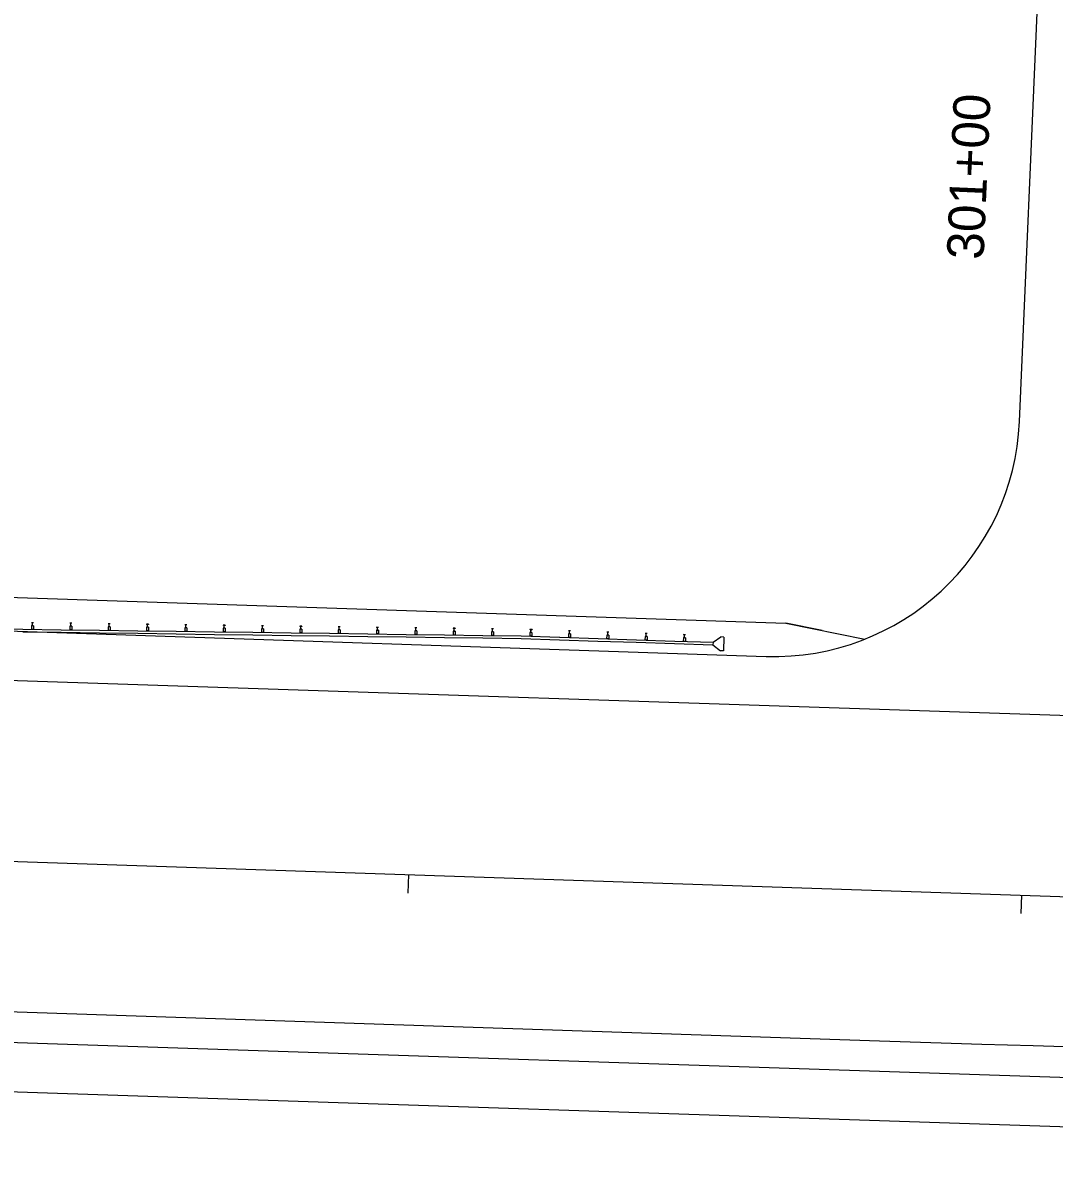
# Model space of a CAD drawing. Extents: x 976639 to 985448, y 1524031 to 1526806.
# Drawn here: x 978186 to 978354.1, y 1526423 to 1526609.3 of the extents above; entities that cross this region are included whole.
import ezdxf

# ---------------------------------------------------------------- set-up
doc = ezdxf.new("R2010")
doc.units = 0
for name, color, linetype in [('B_Steel', 7, 'Continuous'), ('R_Horz Alg', 7, 'Continuous'), ('R_Horz Alg Annot', 7, 'Continuous'), ('R_Horz Alg Annot_Cross Street', 7, 'Continuous'), ('R_Proposed Road_Lane', 7, 'Continuous'), ('R_Proposed Road_Shoulder', 7, 'Continuous'), ('S_WORKING_LINES', 7, 'Continuous')]:
    doc.layers.add(name, color=color, linetype=linetype)

msp = doc.modelspace()

# ---------------------------------------------------------------- linework, layer by layer
at = {"layer": 'B_Steel'}
for p, q in [((978179.73, 1526510.61), (978185.98, 1526510.53)), ((978185.98, 1526510.53), (978192.23, 1526510.44)), ((978187.54, 1526511.11), (978187.39, 1526511.11)), ((978187.39, 1526511.11), (978187.39, 1526511.09)), ((978187.73, 1526511.09), (978187.39, 1526511.09)), ((978187.39, 1526511.09), (978187.39, 1526510.51)), ((978187.72, 1526510.5), (978187.39, 1526510.51)), ((978187.73, 1526511.59), (978187.4, 1526511.59)), ((978187.4, 1526511.59), (978187.4, 1526511.58)), ((978187.55, 1526511.57), (978187.4, 1526511.58)), ((978187.55, 1526511.11), (978187.56, 1526511.57)), ((978187.57, 1526511.11), (978187.57, 1526511.57)), ((978187.73, 1526511.57), (978187.58, 1526511.57)), ((978187.73, 1526511.1), (978187.58, 1526511.1)), ((978187.73, 1526511.09), (978187.72, 1526510.5)), ((978187.73, 1526511.59), (978187.73, 1526511.57)), ((978187.73, 1526511.1), (978187.73, 1526511.09)), ((978192.23, 1526510.44), (978198.48, 1526510.36)), ((978193.64, 1526511.01), (978193.63, 1526510.43)), ((978193.97, 1526510.42), (978193.63, 1526510.43)), ((978193.79, 1526511.02), (978193.64, 1526511.02)), ((978193.64, 1526511.02), (978193.64, 1526511.01)), ((978193.98, 1526511), (978193.64, 1526511.01)), ((978193.98, 1526511.5), (978193.65, 1526511.51)), ((978193.65, 1526511.51), (978193.65, 1526511.49)), ((978193.8, 1526511.49), (978193.65, 1526511.49)), ((978193.8, 1526511.03), (978193.81, 1526511.48)), ((978193.82, 1526511.03), (978193.82, 1526511.48)), ((978193.98, 1526511.49), (978193.83, 1526511.49)), ((978193.98, 1526511.02), (978193.83, 1526511.02)), ((978193.98, 1526511), (978193.97, 1526510.42)), ((978193.98, 1526511.5), (978193.98, 1526511.49)), ((978193.98, 1526511.02), (978193.98, 1526511)), ((978198.48, 1526510.36), (978204.73, 1526510.28)), ((978199.89, 1526510.92), (978199.88, 1526510.34)), ((978200.22, 1526510.34), (978199.88, 1526510.34)), ((978200.04, 1526510.94), (978199.89, 1526510.94)), ((978199.89, 1526510.94), (978199.89, 1526510.92)), ((978200.22, 1526510.92), (978199.89, 1526510.92)), ((978200.23, 1526511.42), (978199.9, 1526511.42)), ((978199.9, 1526511.42), (978199.9, 1526511.41)), ((978200.05, 1526511.41), (978199.9, 1526511.41)), ((978200.05, 1526510.95), (978200.06, 1526511.4)), ((978200.07, 1526510.95), (978200.07, 1526511.4)), ((978200.23, 1526511.4), (978200.08, 1526511.41)), ((978200.23, 1526510.94), (978200.08, 1526510.94)), ((978200.23, 1526510.94), (978200.22, 1526510.92)), ((978200.22, 1526510.92), (978200.22, 1526510.34)), ((978200.23, 1526511.42), (978200.23, 1526511.4)), ((978204.73, 1526510.28), (978210.98, 1526510.19)), ((978206.14, 1526510.84), (978206.13, 1526510.26)), ((978206.47, 1526510.25), (978206.13, 1526510.26)), ((978206.29, 1526510.85), (978206.14, 1526510.86)), ((978206.14, 1526510.86), (978206.14, 1526510.84)), ((978206.47, 1526510.84), (978206.14, 1526510.84)), ((978206.48, 1526511.34), (978206.15, 1526511.34)), ((978206.15, 1526511.34), (978206.15, 1526511.32)), ((978206.3, 1526511.32), (978206.15, 1526511.32)), ((978206.3, 1526510.86), (978206.31, 1526511.31)), ((978206.32, 1526510.86), (978206.32, 1526511.31)), ((978206.47, 1526510.85), (978206.32, 1526510.85)), ((978206.48, 1526511.32), (978206.33, 1526511.32)), ((978206.47, 1526510.85), (978206.47, 1526510.84)), ((978206.47, 1526510.84), (978206.47, 1526510.25)), ((978206.48, 1526511.34), (978206.48, 1526511.32)), ((978210.98, 1526510.19), (978217.23, 1526510.11)), ((978212.39, 1526510.76), (978212.38, 1526510.17)), ((978212.72, 1526510.17), (978212.38, 1526510.17)), ((978212.54, 1526510.77), (978212.39, 1526510.77)), ((978212.39, 1526510.77), (978212.39, 1526510.76)), ((978212.72, 1526510.75), (978212.39, 1526510.76)), ((978212.73, 1526511.25), (978212.4, 1526511.26)), ((978212.4, 1526511.26), (978212.4, 1526511.24)), ((978212.55, 1526511.24), (978212.4, 1526511.24)), ((978212.55, 1526510.78), (978212.56, 1526511.23)), ((978212.57, 1526510.78), (978212.57, 1526511.23)), ((978212.72, 1526510.77), (978212.57, 1526510.77)), ((978212.73, 1526511.24), (978212.58, 1526511.24)), ((978212.72, 1526510.77), (978212.72, 1526510.75)), ((978212.72, 1526510.75), (978212.72, 1526510.17)), ((978212.73, 1526511.25), (978212.73, 1526511.24)), ((978218.64, 1526510.67), (978218.63, 1526510.09)), ((978218.79, 1526510.69), (978218.64, 1526510.69)), ((978218.64, 1526510.69), (978218.64, 1526510.67)), ((978218.97, 1526510.67), (978218.64, 1526510.67)), ((978218.98, 1526511.17), (978218.65, 1526511.17)), ((978218.65, 1526511.17), (978218.65, 1526511.16)), ((978218.8, 1526511.15), (978218.65, 1526511.16)), ((978218.8, 1526510.69), (978218.81, 1526511.15)), ((978218.82, 1526510.69), (978218.82, 1526511.15)), ((978218.97, 1526510.68), (978218.82, 1526510.69)), ((978218.98, 1526511.15), (978218.83, 1526511.15)), ((978218.97, 1526510.68), (978218.97, 1526510.67)), ((978218.97, 1526510.67), (978218.97, 1526510.09)), ((978218.98, 1526511.17), (978218.98, 1526511.15)), ((978224.89, 1526510.59), (978224.88, 1526510.01)), ((978225.04, 1526510.6), (978224.89, 1526510.6)), ((978224.89, 1526510.6), (978224.89, 1526510.59)), ((978225.22, 1526510.58), (978224.89, 1526510.59)), ((978225.23, 1526511.08), (978224.9, 1526511.09)), ((978224.9, 1526511.09), (978224.9, 1526511.07)), ((978225.05, 1526511.07), (978224.9, 1526511.07)), ((978225.05, 1526510.61), (978225.05, 1526511.06)), ((978225.06, 1526510.61), (978225.07, 1526511.06)), ((978225.22, 1526510.6), (978225.07, 1526510.6)), ((978225.23, 1526511.07), (978225.08, 1526511.07)), ((978225.22, 1526510.58), (978225.21, 1526510)), ((978225.22, 1526510.6), (978225.22, 1526510.58)), ((978225.23, 1526511.08), (978225.23, 1526511.07)), ((978231.14, 1526510.51), (978231.13, 1526509.92)), ((978231.29, 1526510.52), (978231.14, 1526510.52)), ((978231.14, 1526510.52), (978231.14, 1526510.51)), ((978231.47, 1526510.5), (978231.14, 1526510.51)), ((978231.48, 1526511), (978231.15, 1526511.01)), ((978231.15, 1526511.01), (978231.15, 1526510.99)), ((978231.3, 1526510.99), (978231.15, 1526510.99)), ((978231.3, 1526510.53), (978231.3, 1526510.98)), ((978231.31, 1526510.53), (978231.32, 1526510.98)), ((978231.47, 1526510.52), (978231.32, 1526510.52)), ((978231.48, 1526510.98), (978231.33, 1526510.99)), ((978231.47, 1526510.5), (978231.46, 1526509.92)), ((978231.47, 1526510.52), (978231.47, 1526510.5)), ((978231.48, 1526511), (978231.48, 1526510.98)), ((978237.39, 1526510.42), (978237.38, 1526509.84)), ((978237.4, 1526510.92), (978237.39, 1526510.91)), ((978237.55, 1526510.9), (978237.39, 1526510.91)), ((978237.54, 1526510.43), (978237.39, 1526510.44)), ((978237.39, 1526510.44), (978237.39, 1526510.42)), ((978237.72, 1526510.42), (978237.39, 1526510.42)), ((978237.73, 1526510.92), (978237.4, 1526510.92)), ((978237.55, 1526510.44), (978237.55, 1526510.9)), ((978237.56, 1526510.44), (978237.57, 1526510.89)), ((978237.72, 1526510.43), (978237.57, 1526510.43)), ((978237.73, 1526510.9), (978237.58, 1526510.9)), ((978237.72, 1526510.42), (978237.71, 1526509.83)), ((978237.72, 1526510.43), (978237.72, 1526510.42)), ((978237.73, 1526510.92), (978237.73, 1526510.9)), ((978243.64, 1526510.34), (978243.63, 1526509.75)), ((978243.98, 1526510.83), (978243.64, 1526510.84)), ((978243.64, 1526510.84), (978243.64, 1526510.82)), ((978243.8, 1526510.82), (978243.64, 1526510.82)), ((978243.79, 1526510.35), (978243.64, 1526510.35)), ((978243.64, 1526510.35), (978243.64, 1526510.34)), ((978243.97, 1526510.33), (978243.64, 1526510.34)), ((978243.8, 1526510.36), (978243.8, 1526510.81)), ((978243.81, 1526510.36), (978243.82, 1526510.81)), ((978243.97, 1526510.35), (978243.82, 1526510.35)), ((978243.98, 1526510.82), (978243.83, 1526510.82)), ((978243.97, 1526510.33), (978243.96, 1526509.75)), ((978243.97, 1526510.35), (978243.97, 1526510.33)), ((978243.98, 1526510.83), (978243.98, 1526510.82)), ((978249.89, 1526510.25), (978249.88, 1526509.67)), ((978250.23, 1526510.75), (978249.89, 1526510.75)), ((978249.89, 1526510.75), (978249.89, 1526510.74)), ((978250.04, 1526510.74), (978249.89, 1526510.74)), ((978250.04, 1526510.27), (978249.89, 1526510.27)), ((978249.89, 1526510.27), (978249.89, 1526510.25)), ((978250.22, 1526510.25), (978249.89, 1526510.25)), ((978250.05, 1526510.27), (978250.05, 1526510.73)), ((978250.06, 1526510.27), (978250.07, 1526510.73)), ((978250.22, 1526510.26), (978250.07, 1526510.27)), ((978250.23, 1526510.73), (978250.08, 1526510.73)), ((978250.22, 1526510.25), (978250.21, 1526509.67)), ((978250.22, 1526510.26), (978250.22, 1526510.25)), ((978250.23, 1526510.75), (978250.23, 1526510.73)), ((978256.14, 1526510.17), (978256.13, 1526509.59)), ((978256.48, 1526510.67), (978256.14, 1526510.67)), ((978256.14, 1526510.67), (978256.14, 1526510.65)), ((978256.29, 1526510.65), (978256.14, 1526510.65)), ((978256.29, 1526510.18), (978256.14, 1526510.18)), ((978256.14, 1526510.18), (978256.14, 1526510.17)), ((978256.47, 1526510.17), (978256.14, 1526510.17)), ((978256.3, 1526510.19), (978256.3, 1526510.64)), ((978256.31, 1526510.19), (978256.32, 1526510.64)), ((978256.47, 1526510.18), (978256.32, 1526510.18)), ((978256.48, 1526510.65), (978256.33, 1526510.65)), ((978256.47, 1526510.17), (978256.46, 1526509.58)), ((978256.47, 1526510.18), (978256.47, 1526510.17)), ((978256.48, 1526510.67), (978256.48, 1526510.65)), ((978262.73, 1526510.58), (978262.39, 1526510.59)), ((978262.39, 1526510.59), (978262.39, 1526510.57)), ((978262.54, 1526510.57), (978262.39, 1526510.57)), ((978262.55, 1526510.11), (978262.55, 1526510.56)), ((978262.56, 1526510.11), (978262.57, 1526510.56)), ((978262.73, 1526510.57), (978262.58, 1526510.57)), ((978262.73, 1526510.58), (978262.73, 1526510.57)), ((978269, 1526510.46), (978268.66, 1526510.47)), ((978268.66, 1526510.47), (978268.66, 1526510.46)), ((978268.81, 1526510.45), (978268.66, 1526510.46)), ((978268.81, 1526509.99), (978268.82, 1526510.44)), ((978268.82, 1526509.99), (978268.84, 1526510.44)), ((978269, 1526510.45), (978268.85, 1526510.45)), ((978269, 1526510.46), (978269, 1526510.45)), ((978275.29, 1526510.25), (978274.95, 1526510.26)), ((978274.95, 1526510.26), (978274.95, 1526510.25)), ((978275.1, 1526510.24), (978274.95, 1526510.25)), ((978275.1, 1526509.78), (978275.11, 1526510.23)), ((978275.11, 1526509.78), (978275.13, 1526510.23)), ((978275.29, 1526510.24), (978275.14, 1526510.24)), ((978275.29, 1526510.25), (978275.29, 1526510.24)), ((978185.97, 1526510.11), (978192.22, 1526510.03)), ((978192.22, 1526510.03), (978198.47, 1526509.94)), ((978198.47, 1526509.94), (978204.72, 1526509.86)), ((978204.72, 1526509.86), (978210.97, 1526509.78)), ((978210.97, 1526509.78), (978217.22, 1526509.69)), ((978217.22, 1526509.69), (978223.47, 1526509.61)), ((978217.23, 1526510.11), (978223.48, 1526510.02)), ((978218.97, 1526510.09), (978218.63, 1526510.09)), ((978223.47, 1526509.61), (978229.72, 1526509.52)), ((978223.48, 1526510.02), (978229.73, 1526509.94)), ((978225.21, 1526510), (978224.88, 1526510.01)), ((978229.72, 1526509.52), (978235.97, 1526509.44)), ((978229.73, 1526509.94), (978235.98, 1526509.86)), ((978231.46, 1526509.92), (978231.13, 1526509.92)), ((978235.97, 1526509.44), (978242.22, 1526509.36)), ((978235.98, 1526509.86), (978242.22, 1526509.77)), ((978237.71, 1526509.83), (978237.38, 1526509.84)), ((978242.22, 1526509.77), (978248.47, 1526509.69)), ((978242.22, 1526509.36), (978248.47, 1526509.27)), ((978243.96, 1526509.75), (978243.63, 1526509.75)), ((978248.47, 1526509.69), (978254.72, 1526509.61)), ((978248.47, 1526509.27), (978254.72, 1526509.19)), ((978250.21, 1526509.67), (978249.88, 1526509.67)), ((978254.72, 1526509.61), (978260.97, 1526509.52)), ((978254.72, 1526509.19), (978260.97, 1526509.1)), ((978256.46, 1526509.58), (978256.13, 1526509.59)), ((978260.97, 1526509.52), (978267.22, 1526509.44)), ((978260.97, 1526509.1), (978267.22, 1526509.02)), ((978262.39, 1526510.09), (978262.38, 1526509.5)), ((978262.71, 1526509.5), (978262.38, 1526509.5)), ((978262.54, 1526510.1), (978262.39, 1526510.1)), ((978262.39, 1526510.1), (978262.39, 1526510.09)), ((978262.72, 1526510.08), (978262.39, 1526510.09)), ((978262.72, 1526510.1), (978262.57, 1526510.1)), ((978262.72, 1526510.08), (978262.71, 1526509.5)), ((978262.72, 1526510.1), (978262.72, 1526510.08)), ((978267.21, 1526509.02), (978273.45, 1526508.81)), ((978267.22, 1526509.44), (978273.47, 1526509.23)), ((978268.65, 1526509.97), (978268.63, 1526509.39)), ((978268.96, 1526509.38), (978268.63, 1526509.39)), ((978268.8, 1526509.98), (978268.65, 1526509.99)), ((978268.65, 1526509.99), (978268.65, 1526509.97)), ((978268.98, 1526509.96), (978268.65, 1526509.97)), ((978268.98, 1526509.98), (978268.83, 1526509.98)), ((978268.98, 1526509.96), (978268.96, 1526509.38)), ((978268.98, 1526509.98), (978268.98, 1526509.96)), ((978273.5, 1526508.81), (978279.75, 1526508.6)), ((978273.51, 1526509.23), (978279.76, 1526509.02)), ((978274.94, 1526509.76), (978274.92, 1526509.18)), ((978275.25, 1526509.17), (978274.92, 1526509.18)), ((978275.09, 1526509.77), (978274.94, 1526509.78)), ((978274.94, 1526509.78), (978274.94, 1526509.76)), ((978275.27, 1526509.75), (978274.94, 1526509.76)), ((978275.27, 1526509.77), (978275.12, 1526509.77)), ((978275.27, 1526509.75), (978275.25, 1526509.17)), ((978275.27, 1526509.77), (978275.27, 1526509.75)), ((978279.75, 1526508.6), (978285.99, 1526508.39)), ((978279.76, 1526509.02), (978286.01, 1526508.81)), ((978281.18, 1526509.55), (978281.16, 1526508.97)), ((978281.5, 1526508.96), (978281.16, 1526508.97)), ((978281.34, 1526509.56), (978281.18, 1526509.57)), ((978281.18, 1526509.57), (978281.18, 1526509.55)), ((978281.52, 1526509.54), (978281.18, 1526509.55)), ((978281.53, 1526510.04), (978281.2, 1526510.05)), ((978281.2, 1526510.05), (978281.2, 1526510.04)), ((978281.35, 1526510.03), (978281.2, 1526510.04)), ((978281.34, 1526509.57), (978281.36, 1526510.03)), ((978281.36, 1526509.57), (978281.37, 1526510.02)), ((978281.52, 1526509.56), (978281.37, 1526509.56)), ((978281.53, 1526510.03), (978281.38, 1526510.03)), ((978281.52, 1526509.54), (978281.5, 1526508.96)), ((978281.52, 1526509.56), (978281.52, 1526509.54)), ((978281.53, 1526510.04), (978281.53, 1526510.03)), ((978285.99, 1526508.39), (978292.24, 1526508.18)), ((978286.01, 1526508.81), (978292.25, 1526508.6)), ((978287.43, 1526509.35), (978287.41, 1526508.76)), ((978287.74, 1526508.75), (978287.41, 1526508.76)), ((978287.58, 1526509.36), (978287.43, 1526509.36)), ((978287.43, 1526509.36), (978287.43, 1526509.35)), ((978287.76, 1526509.33), (978287.43, 1526509.35)), ((978287.78, 1526509.83), (978287.45, 1526509.85)), ((978287.45, 1526509.85), (978287.45, 1526509.83)), ((978287.6, 1526509.82), (978287.45, 1526509.83)), ((978287.59, 1526509.36), (978287.61, 1526509.82)), ((978287.61, 1526509.36), (978287.62, 1526509.82)), ((978287.76, 1526509.35), (978287.61, 1526509.35)), ((978287.78, 1526509.82), (978287.63, 1526509.82)), ((978287.76, 1526509.33), (978287.74, 1526508.75)), ((978287.76, 1526509.35), (978287.76, 1526509.33)), ((978287.78, 1526509.83), (978287.78, 1526509.82)), ((978292.25, 1526508.6), (978298.5, 1526508.39)), ((978293.68, 1526509.14), (978293.66, 1526508.55)), ((978293.99, 1526508.54), (978293.66, 1526508.55)), ((978293.83, 1526509.15), (978293.68, 1526509.15)), ((978293.68, 1526509.15), (978293.68, 1526509.14)), ((978294.01, 1526509.13), (978293.68, 1526509.14)), ((978294.03, 1526509.63), (978293.69, 1526509.64)), ((978293.69, 1526509.64), (978293.69, 1526509.62)), ((978293.84, 1526509.62), (978293.69, 1526509.62)), ((978293.84, 1526509.15), (978293.85, 1526509.61)), ((978293.85, 1526509.15), (978293.87, 1526509.61)), ((978294.01, 1526509.14), (978293.86, 1526509.15)), ((978294.03, 1526509.61), (978293.88, 1526509.61)), ((978294.01, 1526509.13), (978293.99, 1526508.54)), ((978294.01, 1526509.14), (978294.01, 1526509.13)), ((978294.03, 1526509.63), (978294.03, 1526509.61)), ((978298.5, 1526508.39), (978298.49, 1526507.98)), ((978298.5, 1526508.39), (978299.78, 1526509.27)), ((978300.28, 1526509.25), (978299.78, 1526509.27)), ((978300.28, 1526509.25), (978300.2, 1526507)), ((978292.24, 1526508.18), (978298.49, 1526507.98)), ((978298.49, 1526507.98), (978299.71, 1526507.02)), ((978300.21, 1526507), (978299.71, 1526507.02))]:
    msp.add_line(p, q, dxfattribs=at)
at = {"layer": 'R_Horz Alg'}
msp.add_line((976649.79, 1526523.99), (979428.24, 1526431.1), dxfattribs=at)
at = {"layer": 'R_Horz Alg Annot'}
for points in [[(978248.8, 1526467.53), (978248.9, 1526470.53)], [(978348.74, 1526464.19), (978348.84, 1526467.19)]]:
    msp.add_lwpolyline(points, dxfattribs=at)
at = {"layer": 'R_Proposed Road_Lane'}
for p, q in [((978348.47, 1526544.35), (978357.12, 1526744.65)), ((978130.4, 1526517.51), (978310.36, 1526511.5)), ((978316.32, 1526510.3), (978310.36, 1526511.5)), ((978310.36, 1526511.5), (978323.26, 1526508.9)), ((978129.95, 1526504.02), (978549.71, 1526489.99)), ((978547.74, 1526431.02), (977523.32, 1526465.27))]:
    msp.add_line(p, q, dxfattribs=at)
msp.add_arc((978308.5, 1526546.08), 40, 268.0852, 357.5271, dxfattribs=at)
at = {"layer": 'R_Proposed Road_Shoulder'}
for p, q in [((978130.22, 1526512.02), (978307.17, 1526506.1)), ((977891.17, 1526444.97), (978547.48, 1526423.03))]:
    msp.add_line(p, q, dxfattribs=at)
at = {"layer": 'S_WORKING_LINES'}
for p, q in [((976649.79, 1526523.99), (979428.24, 1526431.1)), ((977761.91, 1526462.3), (978325.62, 1526443.45))]:
    msp.add_line(p, q, dxfattribs=at)
msp.add_arc((978553.83, 1533269.64), 6830, 268.085232, 272.579389, dxfattribs=at)

# ---------------------------------------------------------------- texts
at = {"layer": 'R_Horz Alg Annot_Cross Street'}
msp.add_text('301+00', height=6, rotation=87.5271, dxfattribs=at).set_placement((978342.6, 1526570.68))

doc.saveas('drawing.dxf')
